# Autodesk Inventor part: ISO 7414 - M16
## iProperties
IsCustomPart: 0
Created: 2009-02
Part Number: ISO 7414 - M16
Material: Steel
Description: Hexagon nuts for structural bolting with large width across flats, style1 - product B - property class 10
Document SubType Name: Modeling
Standard: ISO 7414
Designer: 904Chiaki
Standard Revision: First edition 1984-11-15
Standards Organization: ISO
Language: en-US
Size Designation: M16
Categories: <MemberInstance><Categories><Category DisplayName="Fasteners" InternalName="e4da775c-781d-43d5-af7c-5136215cf5a6" Mnemonic="FSTN"><Category DisplayName="Nuts" I
Density: 7.85 g/cm^3
Mass: 54.3321 g
Surface Area: 28.0487 cm^2
Volume: 6.92128 cm^3
Author: 904Chiaki
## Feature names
1. Body [Extrusion]
2. Chamfer1 [Revolution]
3. Thread [Hole]
4. Chamfer2
5. Chamfer3
